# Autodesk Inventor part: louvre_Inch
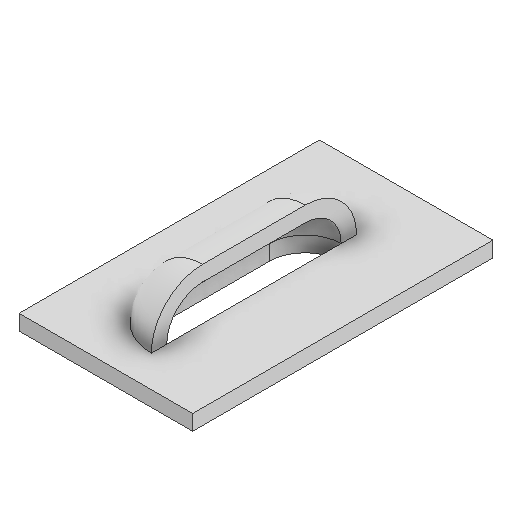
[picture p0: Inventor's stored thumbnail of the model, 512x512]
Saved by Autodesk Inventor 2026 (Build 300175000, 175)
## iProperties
Created: 2025-03
Part Number: louvre_Inch
Material: Generic
Document SubType Name: Sheet Metal
Designer: itools
Density: 1 g/cm^3
Sheet Metal Rule: Default
Appearance: Default
Author: itools
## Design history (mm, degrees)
node "Face1"
  sketch "Sketch1"
    geometry: L1 (11.817, 24.592)-(-5.379, 24.592); L2 (-5.379, 24.592)-(-5.379, -5.155); L3 (-5.379, -5.155)-(11.817, -5.155); L4 (11.817, -5.155)-(11.817, 24.592)
    constraints: 8 end point, 2 parallel, 1 horizontal, 1 perpendicular
sketch "Sketch2"
  geometry: L1 (-1.847, -1.134)-(-1.847, -1.134); L2 (-6.927, -6.214)-(-6.927, -16.374); L3 (-1.847, -21.454)-(-1.847, -21.454); L4 (-1.847, -21.454)-(-1.847, -1.134); L5 (-1.847, -1.134)-(-6.927, -21.454); L6 (-6.927, -1.134)-(-1.847, -21.454); A1 r 5.08 centre (-1.847, -16.374) between (-6.927, -16.374) and (-1.847, -21.454); A2 r 5.08 centre (-1.847, -6.214) between (-1.847, -1.134) and (-6.927, -6.214); 3 further points
  constraints: 12 end point, 4 point on circle, 4 point on line, 4 tangent, 2 centre point, 2 midpoint, 2 parallel, 1 equal radius, 1 horizontal, 1 perpendicular
  dimensions: "d1" = 5.08 radius of A1 (= Width); "Width" = 5.08 distance between parallel lines of L4 L2; "Length" = 20.32 distance of L3.end L1.start
revolve "Revolution1" sketch "Sketch2" stored, may be unused: angle "Angle" = 90 deg
sketch "Sketch3"
  geometry: L1 (15.24, 5.08)-(5.08, 5.08) reference; L2 (5.08, 3.556)-(15.24, 3.556); L3 (1.524, 0)-(18.796, 0); L4 (20.32, 0)-(0, 0) reference; A1 r 5.08 centre (5.08, 0) between (5.08, 5.08) and (0, 0) reference; A2 r 5.08 centre (15.24, 0) between (20.32, 0) and (15.24, 5.08) reference; A3 r 3.556 centre (5.08, 0) between (5.08, 3.556) and (1.524, 0); A4 r 3.556 centre (15.24, 0) between (18.796, 0) and (15.24, 3.556); 1 further point
  constraints: 4 end point, 4 point on circle, 2 centre point, 1 collinear, 2 other
  dimensions: "d5" = 1.524 distance between parallel lines of L1 L2 (= Thickness)
revolve "Revolution2" sketch "Sketch3" stored, may be unused: angle "d6" = 90 deg (= Angle)
sketch "Sketch4"
  geometry: L1 (-5.403, -16.374)-(-5.403, -6.214) reference; L2 (-1.847, -1.134)-(-1.847, -2.658) reference; L3 (-1.847, -2.658)-(-1.847, -19.93); A1 r 3.556 centre (-1.847, -16.374) between (-5.403, -16.374) and (-1.847, -19.93) reference; A2 r 3.556 centre (-1.847, -6.214) between (-1.847, -2.658) and (-5.403, -6.214) reference; 1 further point
  constraints: 2 end point, 1 collinear
extrude "Extrusion1" cut sketch "Sketch4" distance "d7" = 1.524 (= Thickness); taper "d8" = 0 deg
body "Solid1"
face "Plate1" dims "d0" = 1.524 (= Thickness)
other parameters: "Thickness" = 1.524, "BendRadius" = 1.524 (= Thickness), "BendReliefWidth" = 1.524 (= Thickness), "BendReliefDepth" = 0.762 (= 0.5 x Thickness), "CornerReliefSize" = 6.096 (= 4 x Thickness), "SeamGap" = 0.00508, "MinimumRemnant" = 3.048 (= 2 x Thickness), "TransitionRadius" = 1.524 (= BendRadius), "JacobiRadiusSize" = 1.524 (= BendRadius), "GapSize" = 1.524 (= Thickness)
